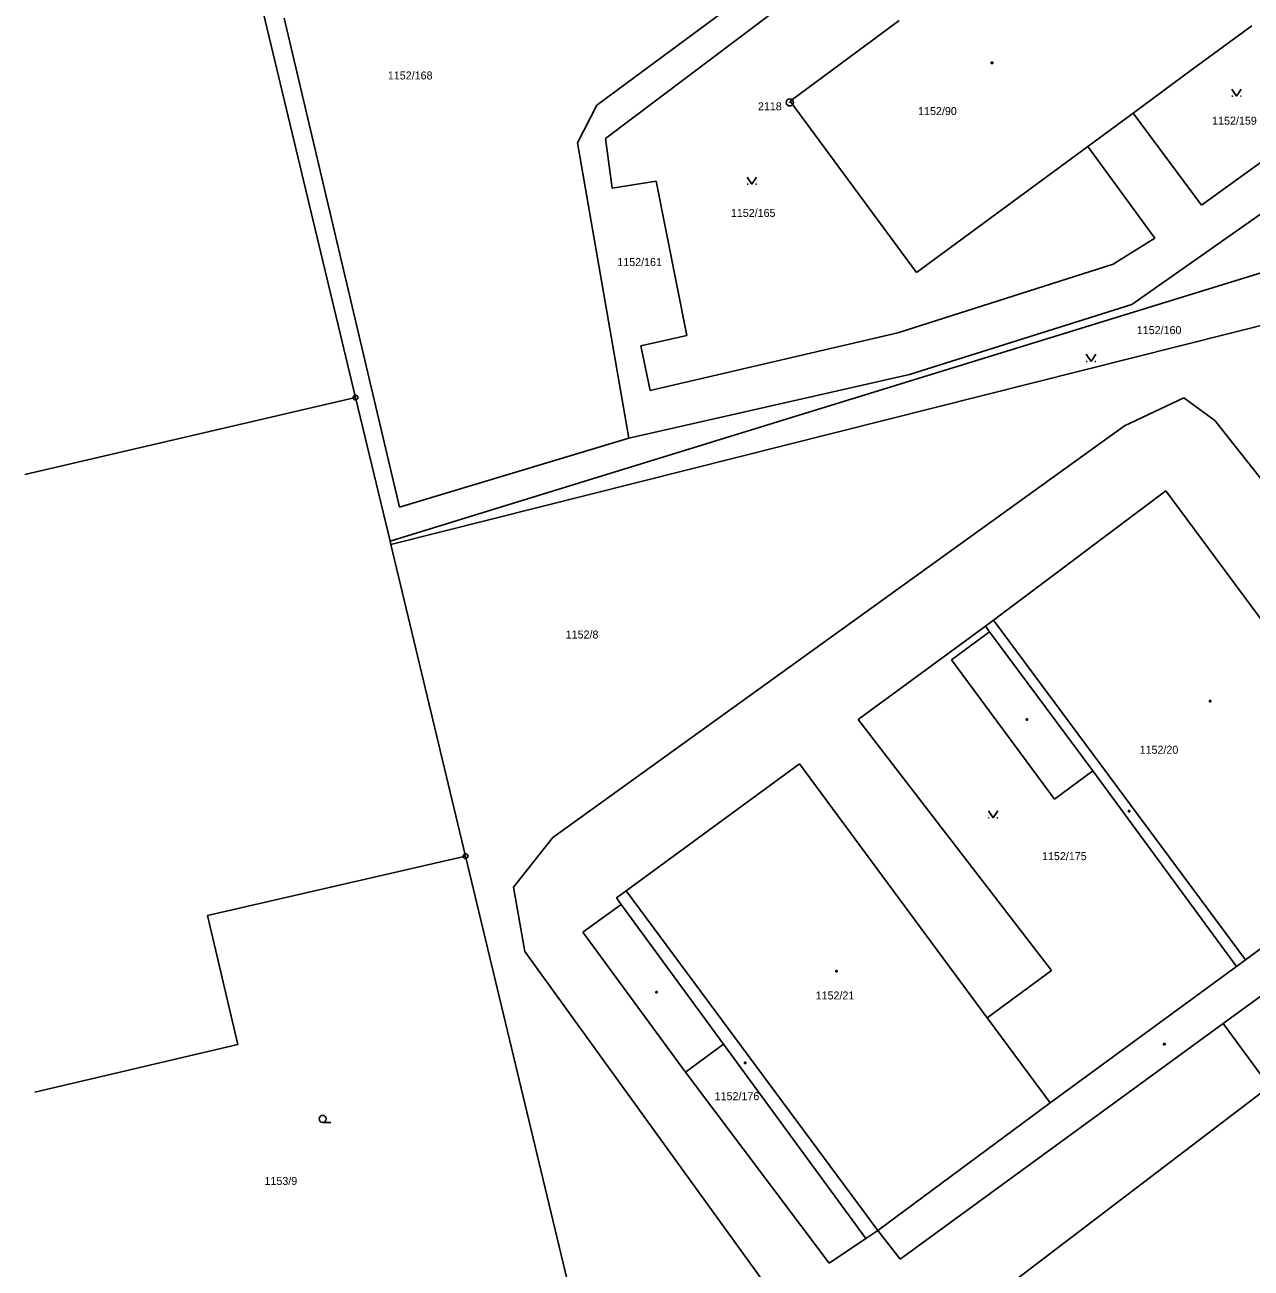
# Model space of a CAD drawing. Extents: x -609709 to -609357, y -1051535 to -1051131.
# Drawn here: x -609702.4 to -609637.3, y -1051388.6 to -1051322.6 of the extents above; entities that cross this region are included whole.
import ezdxf

# ---------------------------------------------------------------- set-up
doc = ezdxf.new("R2010")
doc.units = 0
doc.layers.add('Vrstva 10', color=7, linetype='Continuous')

msp = doc.modelspace()

# ---------------------------------------------------------------- linework, layer by layer
at = {"layer": 'Vrstva 10'}
for p, q in [((-609672.03, -1051326.83), (-609621.69, -1051289.57)), ((-609671.57, -1051328.6), (-609655.2, -1051316.21)), ((-609690.65, -1051318.09), (-609684.83, -1051342.35)), ((-609688.63, -1051322.21), (-609682.51, -1051348.18)), ((-609661.77, -1051326.62), (-609655.98, -1051322.32)), ((-609640.41, -1051324.92), (-609637.26, -1051322.61)), ((-609651.085, -1051324.545), (-609651.01, -1051324.545)), ((-609651.085, -1051324.62), (-609651.085, -1051324.545)), ((-609651.01, -1051324.62), (-609651.085, -1051324.62)), ((-609651.01, -1051324.545), (-609651.01, -1051324.62)), ((-609643.56, -1051327.25), (-609640.41, -1051324.92)), ((-609638.31, -1051325.975), (-609638.06, -1051326.35)), ((-609638.06, -1051326.35), (-609637.81, -1051325.975)), ((-609673.06, -1051328.83), (-609672.03, -1051326.83)), ((-609661.77, -1051326.62), (-609655.05, -1051335.72)), ((-609638.31, -1051326.35), (-609638.26, -1051326.35)), ((-609637.86, -1051326.35), (-609637.81, -1051326.35)), ((-609645.96, -1051329.02), (-609643.56, -1051327.25)), ((-609643.56, -1051327.25), (-609639.92, -1051332.13)), ((-609639.92, -1051332.13), (-609633.64, -1051327.59)), ((-609671.57, -1051328.6), (-609671.22, -1051331.24)), ((-609673.06, -1051328.83), (-609670.32, -1051344.51)), ((-609655.05, -1051335.72), (-609645.96, -1051329.02)), ((-609645.96, -1051329.02), (-609642.41, -1051333.89)), ((-609643.62, -1051337.41), (-609631.47, -1051328.87)), ((-609664.05, -1051330.645), (-609663.8, -1051331.02)), ((-609663.8, -1051331.02), (-609663.55, -1051330.645)), ((-609671.22, -1051331.24), (-609668.87, -1051330.86)), ((-609668.87, -1051330.86), (-609667.24, -1051339.06)), ((-609664.05, -1051331.02), (-609664, -1051331.02)), ((-609663.6, -1051331.02), (-609663.55, -1051331.02)), ((-609683, -1051349.98), (-609630.95, -1051333.93)), ((-609644.61, -1051335.27), (-609642.41, -1051333.89)), ((-609656.05, -1051338.92), (-609644.61, -1051335.27)), ((-609682.96, -1051350.15), (-609629.04, -1051336.58)), ((-609655.43, -1051341.13), (-609643.62, -1051337.41)), ((-609669.69, -1051339.61), (-609667.24, -1051339.06)), ((-609669.19, -1051341.98), (-609656.05, -1051338.92)), ((-609669.69, -1051339.61), (-609669.19, -1051341.98)), ((-609646.04, -1051340.055), (-609645.79, -1051340.43)), ((-609646.04, -1051340.43), (-609645.99, -1051340.43)), ((-609645.79, -1051340.43), (-609645.54, -1051340.055)), ((-609645.59, -1051340.43), (-609645.54, -1051340.43)), ((-609670.32, -1051344.51), (-609655.43, -1051341.13)), ((-609702.39, -1051346.44), (-609684.83, -1051342.35)), ((-609684.83, -1051342.35), (-609683, -1051349.98)), ((-609644.02, -1051343.85), (-609640.87, -1051342.37)), ((-609640.87, -1051342.37), (-609639.21, -1051343.57)), ((-609674.37, -1051365.71), (-609644.02, -1051343.85)), ((-609639.21, -1051343.57), (-609623.41, -1051363.66)), ((-609682.51, -1051348.18), (-609670.32, -1051344.51)), ((-609650.96, -1051354.17), (-609641.82, -1051347.3)), ((-609641.82, -1051347.3), (-609628.43, -1051365.42)), ((-609683, -1051349.98), (-609682.96, -1051350.15)), ((-609682.96, -1051350.15), (-609678.99, -1051366.71)), ((-609658.16, -1051359.45), (-609651.4, -1051354.5)), ((-609651.4, -1051354.5), (-609650.96, -1051354.17)), ((-609651.4, -1051354.5), (-609651.18, -1051354.8)), ((-609650.96, -1051354.17), (-609637.59, -1051372.21)), ((-609653.2, -1051356.29), (-609651.18, -1051354.8)), ((-609651.18, -1051354.8), (-609645.69, -1051362.17)), ((-609653.2, -1051356.29), (-609647.73, -1051363.68)), ((-609639.505, -1051358.435), (-609639.43, -1051358.435)), ((-609639.505, -1051358.51), (-609639.505, -1051358.435)), ((-609639.43, -1051358.51), (-609639.505, -1051358.51)), ((-609639.43, -1051358.435), (-609639.43, -1051358.51)), ((-609658.16, -1051359.45), (-609647.89, -1051372.78)), ((-609649.235, -1051359.415), (-609649.16, -1051359.415)), ((-609649.235, -1051359.49), (-609649.235, -1051359.415)), ((-609649.16, -1051359.49), (-609649.235, -1051359.49)), ((-609649.16, -1051359.415), (-609649.16, -1051359.49)), ((-609670.47, -1051368.55), (-609661.27, -1051361.81)), ((-609661.27, -1051361.81), (-609651.3, -1051375.29)), ((-609647.73, -1051363.68), (-609645.69, -1051362.17)), ((-609645.69, -1051362.17), (-609638.07, -1051372.56)), ((-609651.24, -1051364.295), (-609650.99, -1051364.67)), ((-609650.99, -1051364.67), (-609650.74, -1051364.295)), ((-609643.805, -1051364.285), (-609643.73, -1051364.285)), ((-609643.805, -1051364.36), (-609643.805, -1051364.285)), ((-609643.73, -1051364.36), (-609643.805, -1051364.36)), ((-609643.73, -1051364.285), (-609643.73, -1051364.36)), ((-609651.24, -1051364.67), (-609651.19, -1051364.67)), ((-609650.79, -1051364.67), (-609650.74, -1051364.67)), ((-609676.45, -1051368.36), (-609674.37, -1051365.71)), ((-609692.7, -1051369.86), (-609678.99, -1051366.71)), ((-609678.99, -1051366.71), (-609673.15, -1051391.07)), ((-609637.59, -1051372.21), (-609630.28, -1051366.85)), ((-609676.45, -1051368.36), (-609675.85, -1051371.78)), ((-609670.99, -1051368.93), (-609670.47, -1051368.55)), ((-609670.99, -1051368.93), (-609670.74, -1051369.27)), ((-609670.47, -1051368.55), (-609657.11, -1051386.59)), ((-609638.77, -1051375.59), (-609629.07, -1051368.51)), ((-609672.77, -1051370.75), (-609670.74, -1051369.27)), ((-609670.74, -1051369.27), (-609665.3, -1051376.7)), ((-609692.7, -1051369.86), (-609691.09, -1051376.71)), ((-609672.77, -1051370.75), (-609667.32, -1051378.18)), ((-609675.85, -1051371.78), (-609644.51, -1051415.13)), ((-609638.07, -1051372.56), (-609637.59, -1051372.21)), ((-609659.345, -1051372.775), (-609659.27, -1051372.775)), ((-609659.345, -1051372.85), (-609659.345, -1051372.775)), ((-609659.27, -1051372.85), (-609659.345, -1051372.85)), ((-609659.27, -1051372.775), (-609659.27, -1051372.85)), ((-609651.3, -1051375.29), (-609647.89, -1051372.78)), ((-609647.95, -1051379.81), (-609638.07, -1051372.56)), ((-609668.895, -1051373.895), (-609668.82, -1051373.895)), ((-609668.895, -1051373.97), (-609668.895, -1051373.895)), ((-609668.82, -1051373.97), (-609668.895, -1051373.97)), ((-609668.82, -1051373.895), (-609668.82, -1051373.97)), ((-609655.93, -1051388.12), (-609638.77, -1051375.59)), ((-609651.3, -1051375.29), (-609647.95, -1051379.81)), ((-609638.77, -1051375.59), (-609636.32, -1051378.94)), ((-609701.87, -1051379.24), (-609691.09, -1051376.71)), ((-609667.32, -1051378.18), (-609665.3, -1051376.7)), ((-609665.3, -1051376.7), (-609657.74, -1051387.01)), ((-609641.935, -1051376.655), (-609641.86, -1051376.655)), ((-609641.935, -1051376.73), (-609641.935, -1051376.655)), ((-609641.86, -1051376.73), (-609641.935, -1051376.73)), ((-609641.86, -1051376.655), (-609641.86, -1051376.73)), ((-609664.185, -1051377.645), (-609664.11, -1051377.645)), ((-609664.185, -1051377.72), (-609664.185, -1051377.645)), ((-609664.11, -1051377.645), (-609664.11, -1051377.72)), ((-609667.32, -1051378.18), (-609659.7, -1051388.33)), ((-609664.11, -1051377.72), (-609664.185, -1051377.72)), ((-609653.49, -1051392.02), (-609636.32, -1051378.94)), ((-609657.11, -1051386.59), (-609647.95, -1051379.81)), ((-609686.58, -1051380.85), (-609686.142, -1051380.85)), ((-609657.74, -1051387.01), (-609657.11, -1051386.59)), ((-609657.11, -1051386.59), (-609655.93, -1051388.12)), ((-609659.7, -1051388.33), (-609657.74, -1051387.01))]:
    msp.add_line(p, q, dxfattribs=at)
for centre, radius in [((-609661.78, -1051326.68), 0.188), ((-609661.78, -1051326.68), 0.0025), ((-609684.83, -1051342.35), 0.125), ((-609684.83, -1051342.35), 0.0025), ((-609678.99, -1051366.71), 0.125), ((-609678.99, -1051366.71), 0.0025), ((-609686.58, -1051380.663), 0.188)]:
    msp.add_circle(centre, radius, dxfattribs=at)

# ---------------------------------------------------------------- texts
for s, p in [('1152/168', (-609683.12, -1051325.46)), ('2118', (-609663.473, -1051327.1)), ('1152/90', (-609654.97, -1051327.35)), ('1152/159', (-609639.36, -1051327.86)), ('1152/165', (-609664.91, -1051332.76)), ('1152/161', (-609670.94, -1051335.37)), ('1152/160', (-609643.36, -1051338.985)), ('1152/8', (-609673.68, -1051355.15)), ('1152/20', (-609643.21, -1051361.27)), ('1152/175', (-609648.39, -1051366.92)), ('1152/21', (-609660.41, -1051374.32)), ('1152/176', (-609665.77, -1051379.67)), ('1153/9', (-609689.67, -1051384.17))]:
    msp.add_text(s, height=0.425, dxfattribs=at).set_placement(p)

doc.saveas('drawing.dxf')
